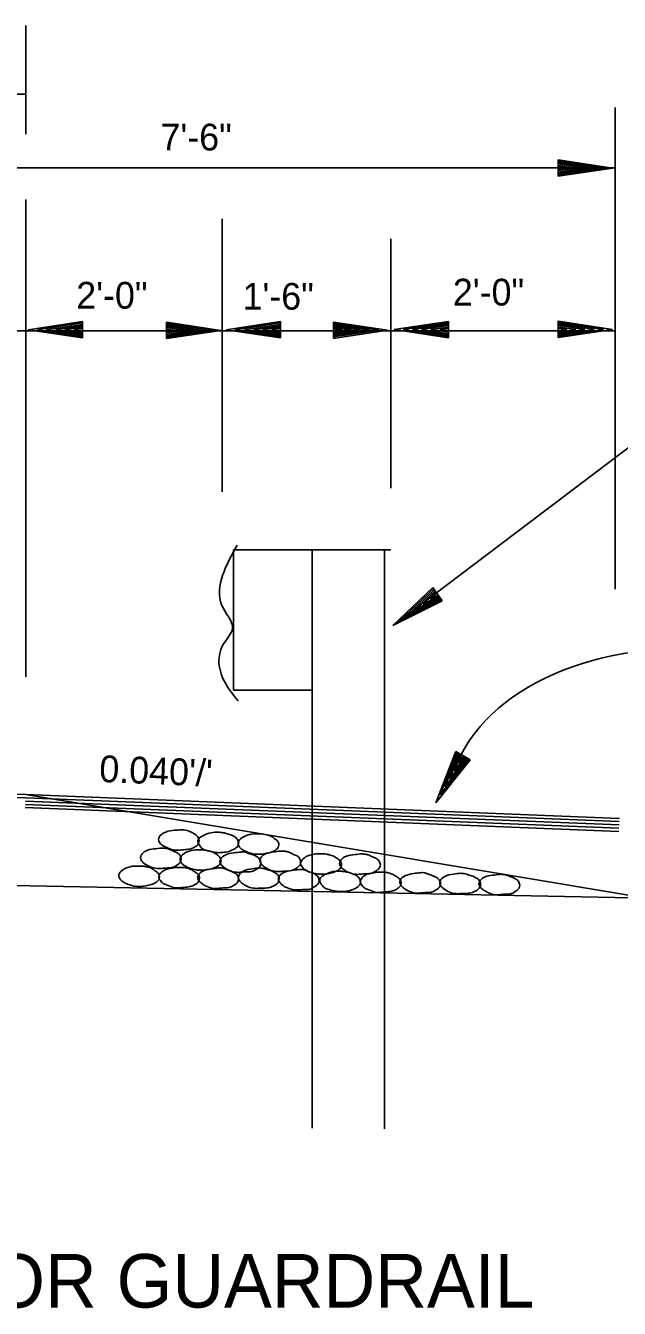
# Model space of a CAD drawing. Extents: x 634177 to 635904, y 289936 to 290970.
# Drawn here: x 635717.99 to 635731.3, y 290939.51 to 290968.24 of the extents above; entities that cross this region are included whole.
import ezdxf

# ---------------------------------------------------------------- set-up
doc = ezdxf.new("R2010")
doc.units = 0
doc.layers.add('Default', color=7, linetype='Continuous')

msp = doc.modelspace()

# ---------------------------------------------------------------- linework, layer by layer
at = {"layer": 'Default'}
for p, q in [((635717.999, 290965.81), (635717.999, 290968.24)), ((635698.559, 290966.706), (635717.999, 290966.706)), ((635731.203, 290955.62), (635731.203, 290966.409)), ((635698.559, 290965.059), (635731.203, 290965.059)), ((635729.925, 290965.235), (635731.143, 290965.05)), ((635729.925, 290965.235), (635729.925, 290964.868)), ((635729.925, 290965.203), (635730.939, 290965.05)), ((635729.925, 290965.172), (635730.73, 290965.05)), ((635729.925, 290965.142), (635730.525, 290965.05)), ((635729.925, 290965.111), (635730.321, 290965.05)), ((635729.925, 290965.079), (635730.117, 290965.05)), ((635729.925, 290964.868), (635731.143, 290965.05)), ((635729.925, 290964.992), (635730.321, 290965.05)), ((635729.925, 290964.931), (635730.73, 290965.05)), ((635729.925, 290964.899), (635730.939, 290965.05)), ((635729.925, 290964.96), (635730.525, 290965.05)), ((635729.925, 290965.023), (635730.117, 290965.05)), ((635717.999, 290953.656), (635717.999, 290964.349)), ((635722.399, 290957.802), (635722.399, 290963.913)), ((635726.173, 290957.882), (635726.173, 290963.468)), ((635719.27, 290961.612), (635718.052, 290961.429)), ((635719.27, 290961.245), (635719.27, 290961.612)), ((635721.148, 290961.599), (635722.365, 290961.415)), ((635721.148, 290961.599), (635721.148, 290961.233)), ((635723.704, 290961.612), (635722.487, 290961.429)), ((635723.704, 290961.245), (635723.704, 290961.612)), ((635724.888, 290961.602), (635726.105, 290961.417)), ((635724.888, 290961.602), (635724.888, 290961.235)), ((635727.466, 290961.614), (635726.249, 290961.432)), ((635727.466, 290961.247), (635727.466, 290961.614)), ((635729.925, 290961.621), (635731.143, 290961.437)), ((635729.925, 290961.621), (635729.925, 290961.254)), ((635713.598, 290961.408), (635726.803, 290961.408)), ((635717.999, 290961.408), (635731.203, 290961.408)), ((635719.27, 290961.245), (635718.052, 290961.429)), ((635719.27, 290961.58), (635718.256, 290961.429)), ((635719.27, 290961.276), (635718.256, 290961.429)), ((635719.27, 290961.548), (635718.465, 290961.429)), ((635719.27, 290961.308), (635718.465, 290961.429)), ((635719.27, 290961.519), (635718.669, 290961.429)), ((635719.27, 290961.337), (635718.669, 290961.429)), ((635719.27, 290961.488), (635718.874, 290961.429)), ((635719.27, 290961.369), (635718.874, 290961.429)), ((635719.27, 290961.456), (635719.078, 290961.429)), ((635719.27, 290961.4), (635719.078, 290961.429)), ((635721.148, 290961.568), (635722.161, 290961.415)), ((635721.148, 290961.536), (635721.952, 290961.415)), ((635721.148, 290961.507), (635721.748, 290961.415)), ((635721.148, 290961.476), (635721.544, 290961.415)), ((635721.148, 290961.444), (635721.34, 290961.415)), ((635721.148, 290961.233), (635722.365, 290961.415)), ((635721.148, 290961.356), (635721.544, 290961.415)), ((635721.148, 290961.296), (635721.952, 290961.415)), ((635721.148, 290961.264), (635722.161, 290961.415)), ((635721.148, 290961.325), (635721.748, 290961.415)), ((635721.148, 290961.388), (635721.34, 290961.415)), ((635723.704, 290961.245), (635722.487, 290961.429)), ((635723.704, 290961.58), (635722.691, 290961.429)), ((635723.704, 290961.276), (635722.691, 290961.429)), ((635723.704, 290961.548), (635722.9, 290961.429)), ((635723.704, 290961.308), (635722.9, 290961.429)), ((635723.704, 290961.519), (635723.104, 290961.429)), ((635723.704, 290961.337), (635723.104, 290961.429)), ((635723.704, 290961.488), (635723.308, 290961.429)), ((635723.704, 290961.369), (635723.308, 290961.429)), ((635723.704, 290961.456), (635723.512, 290961.429)), ((635723.704, 290961.4), (635723.512, 290961.429)), ((635724.888, 290961.57), (635725.901, 290961.417)), ((635724.888, 290961.539), (635725.692, 290961.417)), ((635724.888, 290961.51), (635725.488, 290961.417)), ((635724.888, 290961.478), (635725.284, 290961.417)), ((635724.888, 290961.446), (635725.08, 290961.417)), ((635724.888, 290961.235), (635726.105, 290961.417)), ((635724.888, 290961.359), (635725.284, 290961.417)), ((635724.888, 290961.298), (635725.692, 290961.417)), ((635724.888, 290961.267), (635725.901, 290961.417)), ((635724.888, 290961.327), (635725.488, 290961.417)), ((635724.888, 290961.391), (635725.08, 290961.417)), ((635727.466, 290961.247), (635726.249, 290961.432)), ((635727.466, 290961.582), (635726.453, 290961.432)), ((635727.466, 290961.279), (635726.453, 290961.432)), ((635727.466, 290961.551), (635726.662, 290961.432)), ((635727.466, 290961.31), (635726.662, 290961.432)), ((635727.466, 290961.522), (635726.866, 290961.432)), ((635727.466, 290961.339), (635726.866, 290961.432)), ((635727.466, 290961.49), (635727.07, 290961.432)), ((635727.466, 290961.371), (635727.07, 290961.432)), ((635727.466, 290961.459), (635727.274, 290961.432)), ((635727.466, 290961.403), (635727.274, 290961.432)), ((635729.925, 290961.59), (635730.939, 290961.437)), ((635729.925, 290961.558), (635730.73, 290961.437)), ((635729.925, 290961.529), (635730.525, 290961.437)), ((635729.925, 290961.497), (635730.321, 290961.437)), ((635729.925, 290961.466), (635730.117, 290961.437)), ((635729.925, 290961.254), (635731.143, 290961.437)), ((635729.925, 290961.378), (635730.321, 290961.437)), ((635729.925, 290961.318), (635730.73, 290961.437)), ((635729.925, 290961.286), (635730.939, 290961.437)), ((635729.925, 290961.347), (635730.525, 290961.437)), ((635729.925, 290961.41), (635730.117, 290961.437)), ((635726.253, 290954.822), (635733.099, 290959.996)), ((635722.652, 290956.501), (635722.652, 290953.357)), ((635722.652, 290956.501), (635726.173, 290956.501)), ((635724.414, 290956.501), (635724.414, 290943.545)), ((635726.032, 290956.487), (635726.032, 290943.532)), ((635727.117, 290955.653), (635726.222, 290954.808)), ((635727.136, 290955.63), (635726.388, 290954.923)), ((635727.156, 290955.601), (635726.565, 290955.048)), ((635727.168, 290955.576), (635726.73, 290955.162)), ((635727.323, 290955.357), (635727.117, 290955.653)), ((635727.323, 290955.357), (635726.222, 290954.808)), ((635727.309, 290955.379), (635726.388, 290954.923)), ((635727.287, 290955.406), (635726.565, 290955.048)), ((635727.27, 290955.432), (635726.73, 290955.162)), ((635727.187, 290955.554), (635726.895, 290955.279)), ((635727.251, 290955.459), (635726.895, 290955.279)), ((635727.204, 290955.528), (635727.063, 290955.397)), ((635727.238, 290955.486), (635727.063, 290955.397)), ((635722.652, 290953.357), (635724.414, 290953.357)), ((635727.634, 290951.982), (635727.182, 290950.835)), ((635727.658, 290951.962), (635727.284, 290951.012)), ((635727.687, 290951.948), (635727.388, 290951.194)), ((635727.711, 290951.933), (635727.488, 290951.367)), ((635727.869, 290951.843), (635727.488, 290951.367)), ((635727.741, 290951.918), (635727.592, 290951.547)), ((635727.843, 290951.858), (635727.592, 290951.547)), ((635727.95, 290951.797), (635727.634, 290951.982)), ((635727.77, 290951.901), (635727.697, 290951.722)), ((635727.816, 290951.875), (635727.697, 290951.722)), ((635717.999, 290951.017), (635703.419, 290951.6)), ((635727.95, 290951.797), (635727.182, 290950.835)), ((635727.925, 290951.814), (635727.284, 290951.012)), ((635727.894, 290951.826), (635727.388, 290951.194)), ((635717.999, 290950.944), (635703.419, 290951.527)), ((635717.999, 290951.017), (635731.298, 290950.485)), ((635717.999, 290951.017), (635741.463, 290947.105)), ((635717.987, 290950.725), (635731.286, 290950.193)), ((635717.989, 290950.798), (635731.288, 290950.266)), ((635717.992, 290950.871), (635731.292, 290950.339)), ((635717.995, 290950.944), (635731.294, 290950.412)), ((635698.12, 290949.372), (635736.972, 290948.599))]:
    msp.add_line(p, q, dxfattribs=at)
msp.add_ellipse((635733.492, 290950.299), major_axis=(-6.005, 0.733), ratio=0.655798, start_param=4.712389, end_param=6.093533, dxfattribs=at)
for points in [[(635722.737, 290956.603), (635722.407, 290955.921), (635722.39, 290955.255), (635722.628, 290954.742), (635722.407, 290954.353), (635722.407, 290953.636), (635722.757, 290953.119)], [(635721.442, 290950.225), (635721.282, 290950.216), (635721.087, 290950.157), (635720.985, 290950.065), (635720.971, 290950.012), (635721.019, 290949.914), (635721.078, 290949.871), (635721.189, 290949.817), (635721.345, 290949.773), (635721.427, 290949.773), (635721.544, 290949.783), (635721.675, 290949.798), (635721.777, 290949.837), (635721.865, 290949.919), (635721.879, 290949.982), (635721.85, 290950.07), (635721.787, 290950.128), (635721.719, 290950.167), (635721.612, 290950.211), (635721.544, 290950.225), (635721.442, 290950.225)], [(635722.313, 290950.174), (635722.152, 290950.164), (635721.963, 290950.096), (635721.866, 290950.018), (635721.851, 290949.965), (635721.905, 290949.863), (635721.948, 290949.809), (635722.065, 290949.761), (635722.211, 290949.727), (635722.293, 290949.717), (635722.415, 290949.722), (635722.551, 290949.746), (635722.648, 290949.79), (635722.75, 290949.867), (635722.765, 290949.931), (635722.736, 290950.018), (635722.663, 290950.081), (635722.59, 290950.115), (635722.483, 290950.149), (635722.415, 290950.164), (635722.313, 290950.174)], [(635723.219, 290950.137), (635723.059, 290950.132), (635722.864, 290950.064), (635722.767, 290949.977), (635722.753, 290949.918), (635722.806, 290949.821), (635722.86, 290949.778), (635722.966, 290949.729), (635723.122, 290949.685), (635723.205, 290949.68), (635723.321, 290949.69), (635723.452, 290949.714), (635723.555, 290949.753), (635723.652, 290949.831), (635723.666, 290949.889), (635723.637, 290949.977), (635723.564, 290950.035), (635723.496, 290950.084), (635723.389, 290950.118), (635723.321, 290950.132), (635723.219, 290950.137)], [(635721.04, 290949.82), (635720.869, 290949.8), (635720.68, 290949.752), (635720.583, 290949.659), (635720.568, 290949.606), (635720.617, 290949.504), (635720.675, 290949.46), (635720.782, 290949.402), (635720.937, 290949.363), (635721.015, 290949.363), (635721.137, 290949.373), (635721.273, 290949.382), (635721.375, 290949.431), (635721.462, 290949.513), (635721.477, 290949.577), (635721.448, 290949.664), (635721.375, 290949.722), (635721.307, 290949.752), (635721.2, 290949.795), (635721.137, 290949.815), (635721.04, 290949.82)], [(635721.922, 290949.778), (635721.761, 290949.773), (635721.567, 290949.71), (635721.47, 290949.618), (635721.455, 290949.565), (635721.508, 290949.462), (635721.562, 290949.419), (635721.669, 290949.37), (635721.824, 290949.331), (635721.907, 290949.322), (635722.024, 290949.331), (635722.155, 290949.356), (635722.257, 290949.394), (635722.354, 290949.472), (635722.369, 290949.535), (635722.34, 290949.623), (635722.267, 290949.681), (635722.199, 290949.725), (635722.092, 290949.759), (635722.024, 290949.773), (635721.922, 290949.778)], [(635722.82, 290949.729), (635722.66, 290949.714), (635722.465, 290949.661), (635722.363, 290949.569), (635722.348, 290949.515), (635722.402, 290949.418), (635722.455, 290949.374), (635722.567, 290949.311), (635722.718, 290949.277), (635722.8, 290949.277), (635722.917, 290949.287), (635723.058, 290949.292), (635723.155, 290949.34), (635723.248, 290949.423), (635723.262, 290949.486), (635723.233, 290949.573), (635723.165, 290949.632), (635723.092, 290949.666), (635722.99, 290949.7), (635722.922, 290949.729), (635722.82, 290949.729)], [(635723.704, 290949.752), (635723.544, 290949.732), (635723.354, 290949.684), (635723.257, 290949.591), (635723.243, 290949.538), (635723.296, 290949.436), (635723.35, 290949.392), (635723.457, 290949.334), (635723.612, 290949.295), (635723.69, 290949.295), (635723.811, 290949.304), (635723.943, 290949.314), (635724.049, 290949.363), (635724.142, 290949.445), (635724.156, 290949.509), (635724.127, 290949.596), (635724.054, 290949.654), (635723.981, 290949.684), (635723.879, 290949.732), (635723.806, 290949.747), (635723.704, 290949.752)], [(635724.623, 290949.688), (635724.463, 290949.684), (635724.268, 290949.62), (635724.171, 290949.528), (635724.156, 290949.475), (635724.21, 290949.373), (635724.263, 290949.329), (635724.37, 290949.28), (635724.526, 290949.241), (635724.608, 290949.232), (635724.725, 290949.241), (635724.856, 290949.266), (635724.958, 290949.304), (635725.055, 290949.382), (635725.07, 290949.445), (635725.041, 290949.533), (635724.968, 290949.591), (635724.9, 290949.635), (635724.793, 290949.669), (635724.725, 290949.684), (635724.623, 290949.688)], [(635725.489, 290949.688), (635725.328, 290949.669), (635725.139, 290949.62), (635725.042, 290949.528), (635725.027, 290949.475), (635725.081, 290949.373), (635725.134, 290949.329), (635725.241, 290949.27), (635725.396, 290949.232), (635725.474, 290949.232), (635725.596, 290949.241), (635725.727, 290949.251), (635725.834, 290949.3), (635725.926, 290949.382), (635725.941, 290949.445), (635725.912, 290949.533), (635725.839, 290949.591), (635725.766, 290949.62), (635725.664, 290949.669), (635725.591, 290949.684), (635725.489, 290949.688)], [(635720.544, 290949.415), (635720.383, 290949.411), (635720.189, 290949.343), (635720.097, 290949.255), (635720.082, 290949.197), (635720.131, 290949.1), (635720.189, 290949.056), (635720.291, 290949.007), (635720.451, 290948.963), (635720.529, 290948.959), (635720.651, 290948.968), (635720.782, 290948.993), (635720.884, 290949.032), (635720.976, 290949.109), (635720.991, 290949.168), (635720.962, 290949.255), (635720.889, 290949.313), (635720.821, 290949.362), (635720.714, 290949.396), (635720.646, 290949.411), (635720.544, 290949.415)], [(635721.443, 290949.387), (635721.283, 290949.373), (635721.088, 290949.314), (635720.996, 290949.227), (635720.981, 290949.168), (635721.03, 290949.071), (635721.078, 290949.027), (635721.19, 290948.979), (635721.341, 290948.93), (635721.423, 290948.93), (635721.545, 290948.94), (635721.681, 290948.959), (635721.778, 290948.993), (635721.875, 290949.081), (635721.89, 290949.139), (635721.861, 290949.227), (635721.788, 290949.285), (635721.715, 290949.329), (635721.613, 290949.368), (635721.545, 290949.382), (635721.443, 290949.387)], [(635722.317, 290949.374), (635722.156, 290949.355), (635721.962, 290949.301), (635721.865, 290949.214), (635721.85, 290949.155), (635721.904, 290949.058), (635721.957, 290949.015), (635722.064, 290948.956), (635722.215, 290948.917), (635722.297, 290948.917), (635722.419, 290948.927), (635722.55, 290948.937), (635722.652, 290948.98), (635722.749, 290949.068), (635722.764, 290949.126), (635722.735, 290949.214), (635722.662, 290949.272), (635722.589, 290949.306), (635722.482, 290949.345), (635722.419, 290949.369), (635722.317, 290949.374)], [(635723.231, 290949.375), (635723.066, 290949.356), (635722.872, 290949.302), (635722.775, 290949.215), (635722.76, 290949.156), (635722.813, 290949.059), (635722.867, 290949.015), (635722.979, 290948.952), (635723.129, 290948.918), (635723.207, 290948.918), (635723.329, 290948.923), (635723.465, 290948.938), (635723.567, 290948.981), (635723.659, 290949.069), (635723.674, 290949.127), (635723.644, 290949.215), (635723.572, 290949.273), (635723.499, 290949.307), (635723.397, 290949.341), (635723.333, 290949.36), (635723.231, 290949.375)], [(635724.127, 290949.339), (635723.957, 290949.319), (635723.772, 290949.27), (635723.67, 290949.178), (635723.656, 290949.125), (635723.709, 290949.023), (635723.763, 290948.979), (635723.875, 290948.921), (635724.025, 290948.882), (635724.103, 290948.882), (635724.224, 290948.891), (635724.365, 290948.901), (635724.463, 290948.95), (635724.555, 290949.032), (635724.569, 290949.096), (635724.54, 290949.183), (635724.467, 290949.241), (635724.399, 290949.27), (635724.292, 290949.309), (635724.229, 290949.334), (635724.127, 290949.339)], [(635725.043, 290949.301), (635724.883, 290949.292), (635724.693, 290949.223), (635724.596, 290949.146), (635724.582, 290949.092), (635724.635, 290948.99), (635724.679, 290948.937), (635724.795, 290948.888), (635724.941, 290948.854), (635725.024, 290948.844), (635725.145, 290948.849), (635725.281, 290948.874), (635725.379, 290948.917), (635725.481, 290948.995), (635725.495, 290949.058), (635725.466, 290949.146), (635725.393, 290949.209), (635725.32, 290949.243), (635725.213, 290949.277), (635725.145, 290949.292), (635725.043, 290949.301)], [(635725.957, 290949.283), (635725.797, 290949.268), (635725.602, 290949.21), (635725.51, 290949.122), (635725.495, 290949.064), (635725.544, 290948.967), (635725.593, 290948.923), (635725.704, 290948.874), (635725.855, 290948.826), (635725.938, 290948.826), (635726.059, 290948.836), (635726.195, 290948.855), (635726.292, 290948.889), (635726.39, 290948.976), (635726.404, 290949.035), (635726.375, 290949.122), (635726.302, 290949.181), (635726.229, 290949.224), (635726.127, 290949.263), (635726.059, 290949.278), (635725.957, 290949.283)], [(635726.844, 290949.268), (635726.684, 290949.249), (635726.489, 290949.195), (635726.392, 290949.108), (635726.377, 290949.049), (635726.431, 290948.952), (635726.484, 290948.908), (635726.591, 290948.85), (635726.742, 290948.811), (635726.825, 290948.811), (635726.946, 290948.821), (635727.077, 290948.831), (635727.179, 290948.874), (635727.277, 290948.962), (635727.291, 290949.02), (635727.262, 290949.108), (635727.189, 290949.166), (635727.116, 290949.2), (635727.009, 290949.239), (635726.946, 290949.263), (635726.844, 290949.268)], [(635727.744, 290949.256), (635727.579, 290949.236), (635727.384, 290949.183), (635727.287, 290949.096), (635727.272, 290949.037), (635727.326, 290948.94), (635727.379, 290948.896), (635727.491, 290948.833), (635727.642, 290948.799), (635727.72, 290948.799), (635727.841, 290948.804), (635727.977, 290948.818), (635728.079, 290948.862), (635728.172, 290948.95), (635728.186, 290949.008), (635728.157, 290949.096), (635728.084, 290949.154), (635728.011, 290949.188), (635727.909, 290949.222), (635727.846, 290949.241), (635727.744, 290949.256)], [(635728.621, 290949.231), (635728.451, 290949.211), (635728.261, 290949.163), (635728.164, 290949.07), (635728.15, 290949.017), (635728.203, 290948.92), (635728.257, 290948.876), (635728.364, 290948.818), (635728.519, 290948.774), (635728.597, 290948.774), (635728.718, 290948.789), (635728.854, 290948.793), (635728.956, 290948.842), (635729.049, 290948.925), (635729.063, 290948.988), (635729.034, 290949.075), (635728.961, 290949.134), (635728.888, 290949.168), (635728.786, 290949.206), (635728.718, 290949.226), (635728.621, 290949.231)]]:
    msp.add_spline(points, degree=3, dxfattribs=at)

# ---------------------------------------------------------------- texts
for s, height, p in [('7\'-6"', 0.6, (635721.016, 290965.444)), ('2\'-0"', 0.6, (635719.129, 290961.901)), ('1\'-6"', 0.6, (635722.854, 290961.879)), ('2\'-0"', 0.6, (635727.566, 290961.971)), ('WIDENING FOR GUARDRAIL', 1.2, (635707.552, 290939.527))]:
    msp.add_text(s, height=height, dxfattribs=at).set_placement(p)
msp.add_text("0.040'/'", height=0.6, rotation=357.7094, dxfattribs=at).set_placement((635719.636, 290951.3))

doc.saveas('drawing.dxf')
